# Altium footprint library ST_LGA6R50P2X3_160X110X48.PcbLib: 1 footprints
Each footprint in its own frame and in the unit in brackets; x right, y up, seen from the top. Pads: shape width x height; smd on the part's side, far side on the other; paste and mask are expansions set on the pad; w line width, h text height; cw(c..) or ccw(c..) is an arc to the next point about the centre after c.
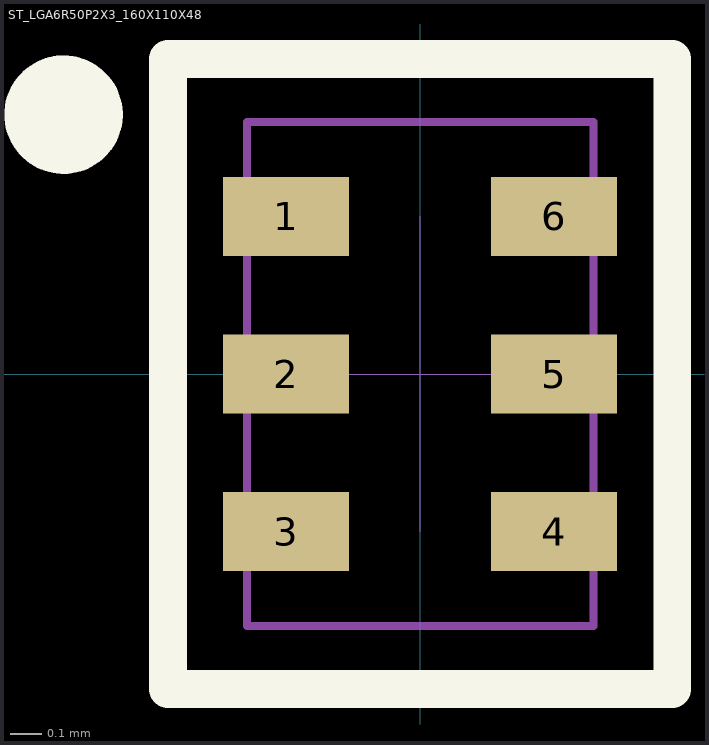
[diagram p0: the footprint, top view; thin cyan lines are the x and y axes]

## ST_LGA6R50P2X3_160X110X48 [mm] "ST_LGA6R50P2X3_160X110X48"
pads (6):
  rect 0.4x0.25 smd paste-20 mask+0.025: 1(-0.425,0.5) 2(-0.425,0) 3(-0.425,-0.5) 4(0.425,-0.5) 5(0.425,0) 6(0.425,0.5)
Top Overlay:
  circle w0.2: c-1.132,0.823 r0.088
  lines w0.12: -0.8,-1 0.8,-1 0.8,1 -0.8,1 -0.8,-1
Top Paste:
  rectangle: -0.4,0.4 -0.2,0.6
  rectangle: 0.2,0.4 0.4,0.6
  rectangle: 0.2,-0.1 0.4,0.1
  rectangle: -0.4,-0.1 -0.2,0.1
  rectangle: -0.4,-0.6 -0.2,-0.4
  rectangle: 0.2,-0.6 0.4,-0.4
Mechanical 5:
  text "5" at 0.725,-0.05 h0.1
  text "6" at 0.725,0.45 h0.1
  text "2" at -0.805,-0.03 h0.1
  text "3" at -0.805,-0.53 h0.1
  text "4" at 0.725,-0.55 h0.1
  text "1" at -0.805,0.47 h0.1
Mechanical 6:
  lines w0.025: -0.55,-0.8 -0.55,0.8 0.55,0.8 0.55,-0.8 -0.55,-0.8
Mechanical 7:
  lines w0.025: -0.55,-0.8 0.55,-0.8 0.55,0.8 -0.55,0.8 -0.55,-0.8
Mechanical 15:
  lines w0.001: -0.5,0 0.5,0 ; 0,-0.5 0,0.5
3D body: height 0.45, standoff 0, extent -0.55,-0.8 0.55,0.8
